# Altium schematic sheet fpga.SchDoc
size A2
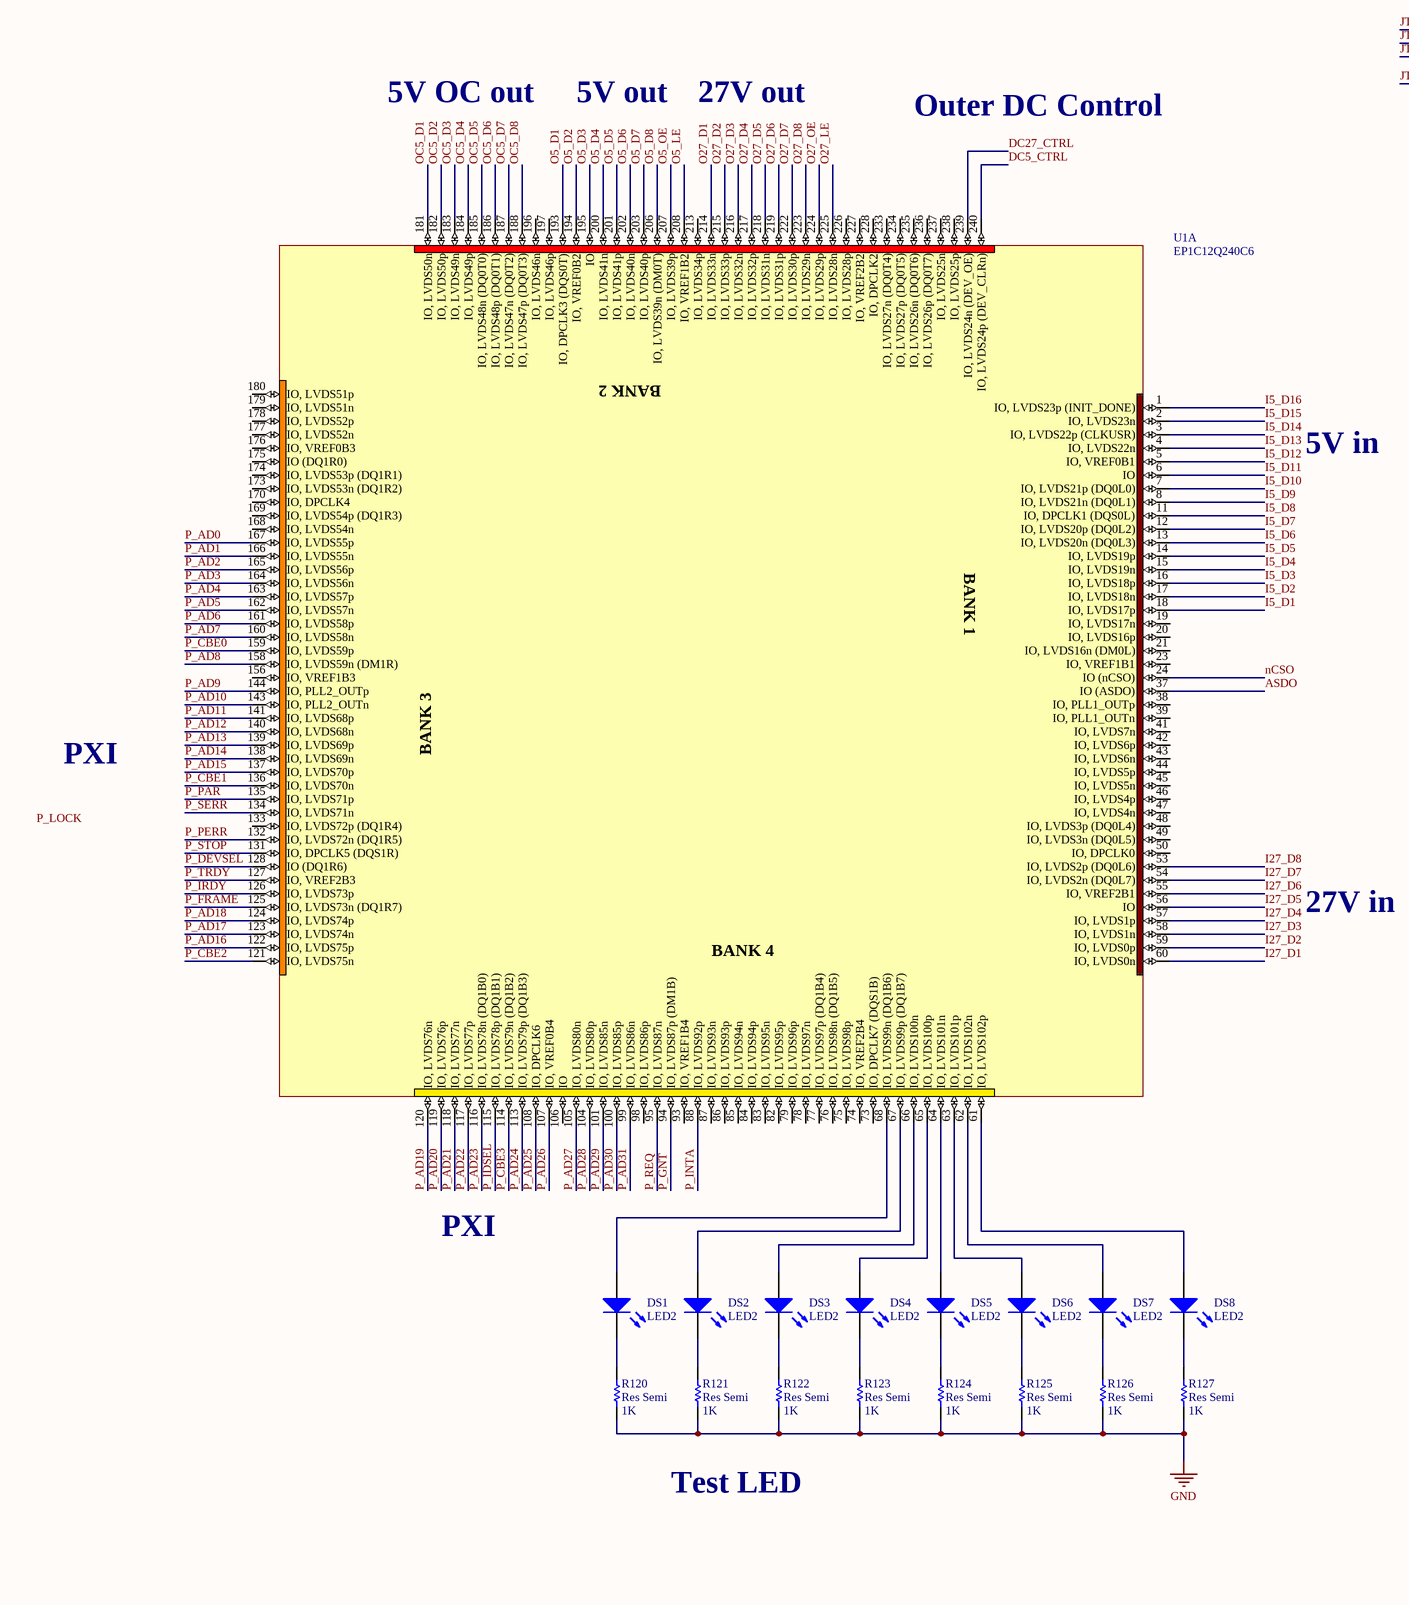
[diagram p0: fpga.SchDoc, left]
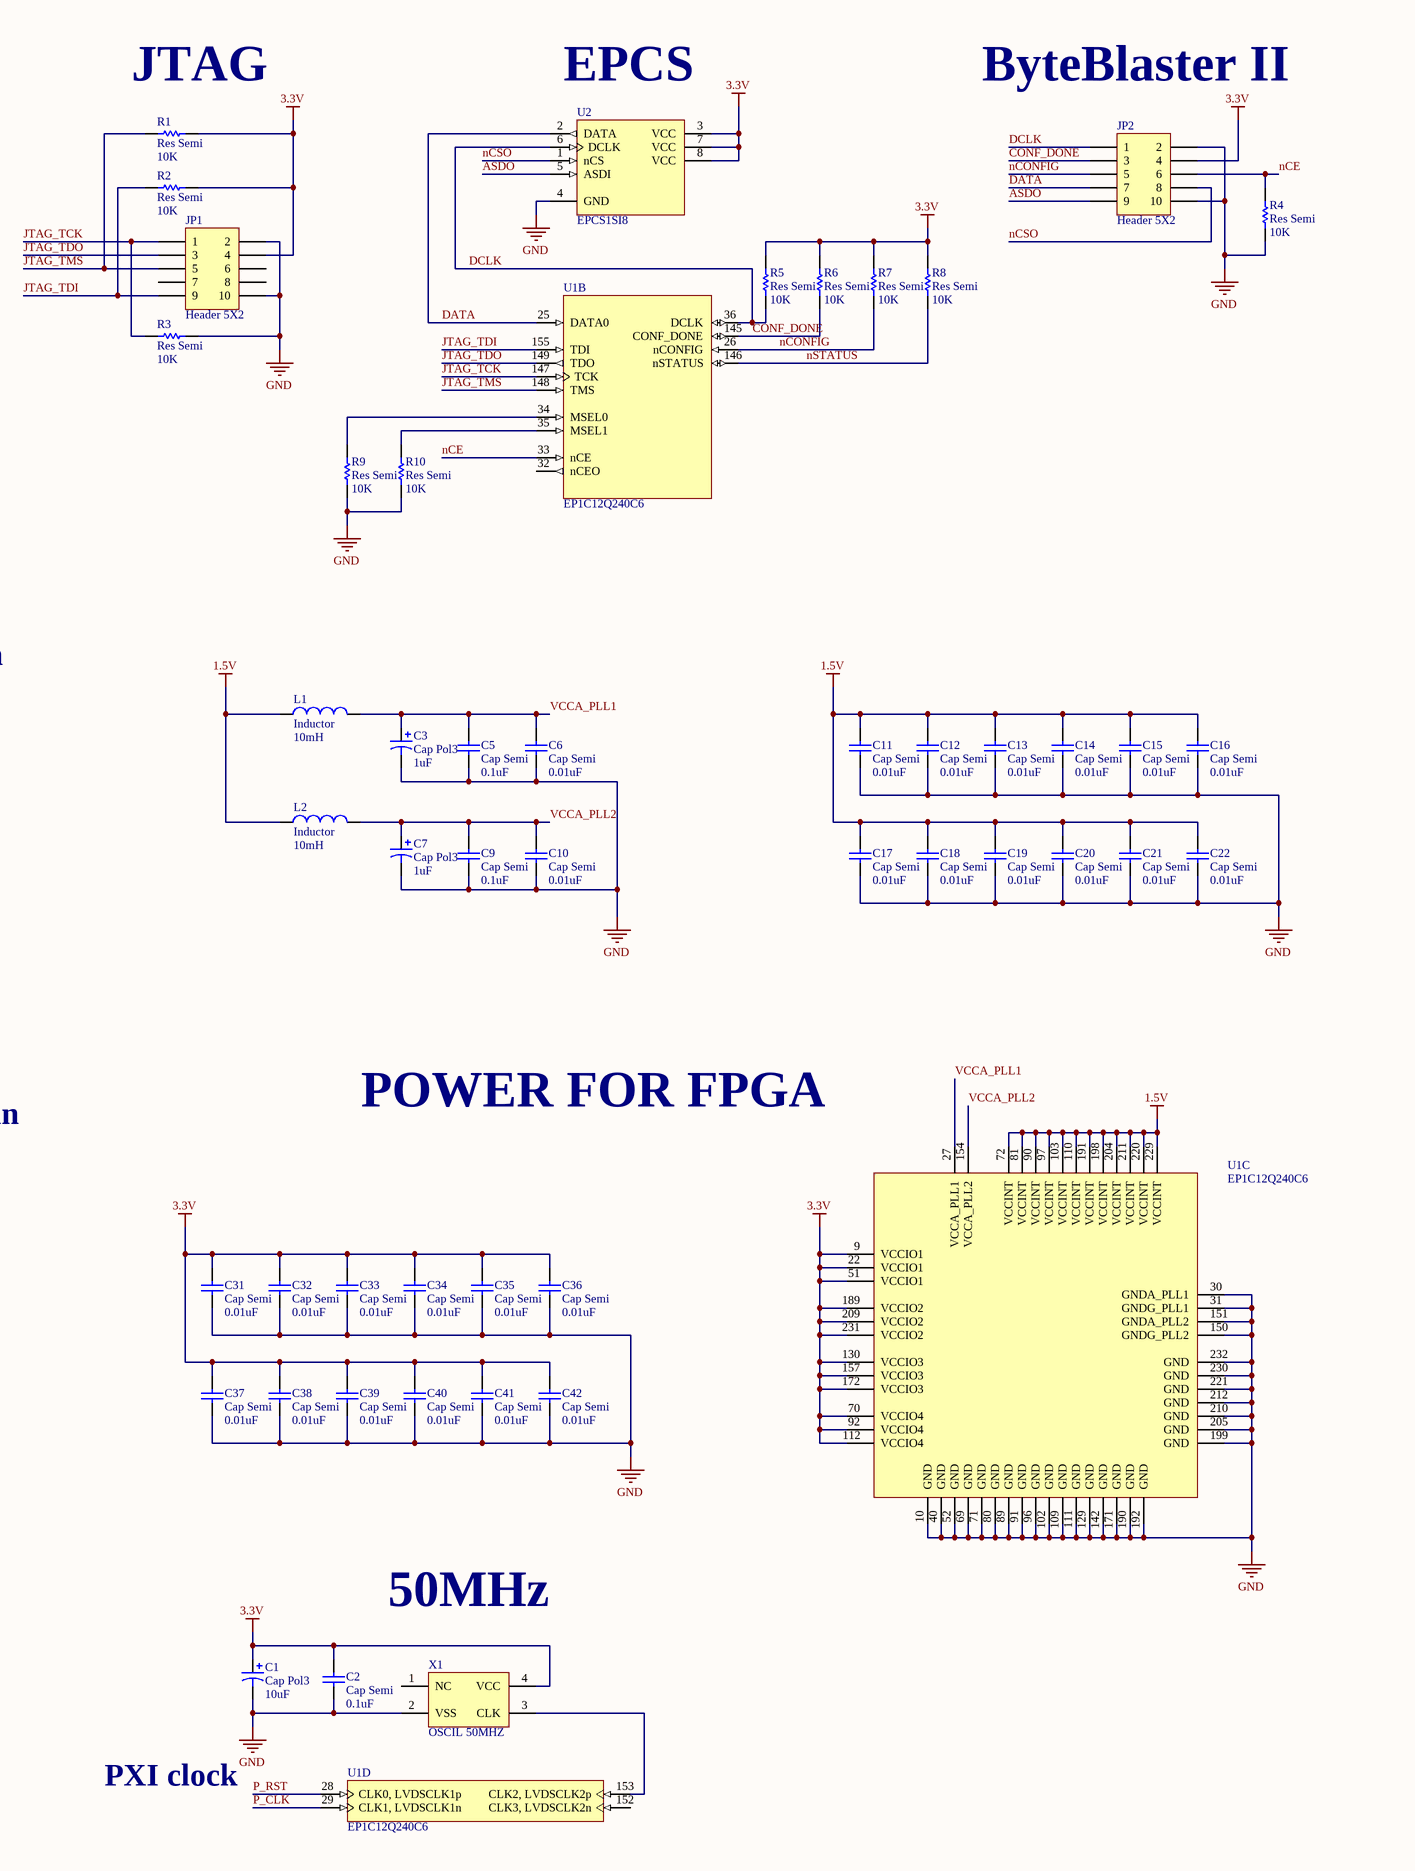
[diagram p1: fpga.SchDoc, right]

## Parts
C1  Cap Pol3  value 10uF  [CC3216-1206]
C2  Cap Semi  value 0.1uF  [1608[0603]]
C3  Cap Pol3  value 1uF  [CC3216-1206]
C5  Cap Semi  value 0.1uF  [1608[0603]]
C6  Cap Semi  value 0.01uF  [1608[0603]]
C7  Cap Pol3  value 1uF  [CC3216-1206]
C9  Cap Semi  value 0.1uF  [1608[0603]]
C10  Cap Semi  value 0.01uF  [1608[0603]]
C11  Cap Semi  value 0.01uF  [1608[0603]]
C12  Cap Semi  value 0.01uF  [1608[0603]]
C13  Cap Semi  value 0.01uF  [1608[0603]]
C14  Cap Semi  value 0.01uF  [1608[0603]]
C15  Cap Semi  value 0.01uF  [1608[0603]]
C16  Cap Semi  value 0.01uF  [1608[0603]]
C17  Cap Semi  value 0.01uF  [1608[0603]]
C18  Cap Semi  value 0.01uF  [1608[0603]]
C19  Cap Semi  value 0.01uF  [1608[0603]]
C20  Cap Semi  value 0.01uF  [1608[0603]]
C21  Cap Semi  value 0.01uF  [1608[0603]]
C22  Cap Semi  value 0.01uF  [1608[0603]]
C31  Cap Semi  value 0.01uF  [1608[0603]]
C32  Cap Semi  value 0.01uF  [1608[0603]]
C33  Cap Semi  value 0.01uF  [1608[0603]]
C34  Cap Semi  value 0.01uF  [1608[0603]]
C35  Cap Semi  value 0.01uF  [1608[0603]]
C36  Cap Semi  value 0.01uF  [1608[0603]]
C37  Cap Semi  value 0.01uF  [1608[0603]]
C38  Cap Semi  value 0.01uF  [1608[0603]]
C39  Cap Semi  value 0.01uF  [1608[0603]]
C40  Cap Semi  value 0.01uF  [1608[0603]]
C41  Cap Semi  value 0.01uF  [1608[0603]]
C42  Cap Semi  value 0.01uF  [1608[0603]]
DS1  LED2  [CC1608-0603]
DS2  LED2  [CC1608-0603]
DS3  LED2  [CC1608-0603]
DS4  LED2  [CC1608-0603]
DS5  LED2  [CC1608-0603]
DS6  LED2  [CC1608-0603]
DS7  LED2  [CC1608-0603]
DS8  LED2  [CC1608-0603]
JP1  Header 5X2  [HDR2X5]
JP2  Header 5X2  [HDR2X5]
L1  Inductor  value 10mH  [C1608-0603]
L2  Inductor  value 10mH  [C1608-0603]
R1  Res Semi  value 10K  [1608[0603]]
R2  Res Semi  value 10K  [1608[0603]]
R3  Res Semi  value 10K  [1608[0603]]
R4  Res Semi  value 10K  [1608[0603]]
R5  Res Semi  value 10K  [1608[0603]]
R6  Res Semi  value 10K  [1608[0603]]
R7  Res Semi  value 10K  [1608[0603]]
R8  Res Semi  value 10K  [1608[0603]]
R9  Res Semi  value 10K  [1608[0603]]
R10  Res Semi  value 10K  [1608[0603]]
R120  Res Semi  value 1K  [1608[0603]]
R121  Res Semi  value 1K  [1608[0603]]
R122  Res Semi  value 1K  [1608[0603]]
R123  Res Semi  value 1K  [1608[0603]]
R124  Res Semi  value 1K  [1608[0603]]
R125  Res Semi  value 1K  [1608[0603]]
R126  Res Semi  value 1K  [1608[0603]]
R127  Res Semi  value 1K  [1608[0603]]
U1  EP1C12Q240C6  [PQFP240]  (parts A,B,C,D of 4)
U2  EPCS1SI8  [SOIC8_L]
X1  OSCIL 50MHZ  [OSC -BIG]

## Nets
1.5V: C11.2 C12.2 C13.2 C14.2 C15.2 C16.2 C17.2 C18.2 C19.2 C20.2 C21.2 C22.2 L1.1 L2.1 U1.72(VCCINT) U1.81(VCCINT) U1.90(VCCINT) U1.97(VCCINT) U1.103(VCCINT) U1.110(VCCINT) U1.191(VCCINT) U1.198(VCCINT) U1.204(VCCINT) U1.211(VCCINT) U1.220(VCCINT) U1.229(VCCINT)
3.3V: C1.1 C2.2 C31.2 C32.2 C33.2 C34.2 C35.2 C36.2 C37.2 C38.2 C39.2 C40.2 C41.2 C42.2 JP1.4 JP2.4 R1.2 R2.2 R5.1 R6.1 R7.1 R8.1 U1.9(VCCIO1) U1.22(VCCIO1) U1.51(VCCIO1) U1.70(VCCIO4) U1.92(VCCIO4) U1.112(VCCIO4) U1.130(VCCIO3) U1.157(VCCIO3) U1.172(VCCIO3) U1.189(VCCIO2) U1.209(VCCIO2) U1.231(VCCIO2) U2.3(VCC) U2.7(VCC) U2.8(VCC) X1.4(VCC)
GND: C1.2 C2.1 C3.2 C5.1 C6.1 C7.2 C9.1 C10.1 C11.1 C12.1 C13.1 C14.1 C15.1 C16.1 C17.1 C18.1 C19.1 C20.1 C21.1 C22.1 C31.1 C32.1 C33.1 C34.1 C35.1 C36.1 C37.1 C38.1 C39.1 C40.1 C41.1 C42.1 JP1.2 JP1.10 JP2.2 JP2.10 R3.2 R4.1 R9.2 R10.2 R120.2 R121.2 R122.2 R123.2 R124.2 R125.2 R126.2 R127.2 U1.10(GND) U1.30(GNDA_PLL1) U1.31(GNDG_PLL1) U1.40(GND) U1.52(GND) U1.69(GND) U1.71(GND) U1.80(GND) U1.89(GND) U1.91(GND) U1.96(GND) U1.102(GND) U1.109(GND) U1.111(GND) U1.129(GND) U1.142(GND) U1.150(GNDG_PLL2) U1.151(GNDA_PLL2) U1.171(GND) U1.190(GND) U1.192(GND) U1.199(GND) U1.205(GND) U1.210(GND) U1.212(GND) U1.221(GND) U1.230(GND) U1.232(GND) U2.4(GND) X1.2(VSS)
ASDO: JP2.9 U1.37(IO_(ASDO)) U2.5(ASDI)
CONF_DONE: JP2.3 R6.2 U1.145(CONF_DONE)
DATA: JP2.7 U1.25(DATA0) U2.2(DATA)
DC5_CTRL: U1.240(IO,_LVDS24p_(DEV_CLRn))
DC27_CTRL: U1.239(IO,_LVDS24n_(DEV_OE))
DCLK: JP2.1 R5.2 U1.36(DCLK) U2.6(DCLK)
I5_D1: U1.18(IO,_LVDS17p)
I5_D2: U1.17(IO,_LVDS18n)
I5_D3: U1.16(IO,_LVDS18p)
I5_D4: U1.15(IO,_LVDS19n)
I5_D5: U1.14(IO,_LVDS19p)
I5_D6: U1.13(IO,_LVDS20n_(DQ0L3))
I5_D7: U1.12(IO,_LVDS20p_(DQ0L2))
I5_D8: U1.11(IO,_DPCLK1_(DQS0L))
I5_D9: U1.8(IO,_LVDS21n_(DQ0L1))
I5_D10: U1.7(IO,_LVDS21p_(DQ0L0))
I5_D11: U1.6(IO)
I5_D12: U1.5(IO,_VREF0B1)
I5_D13: U1.4(IO,_LVDS22n)
I5_D14: U1.3(IO,_LVDS22p_(CLKUSR))
I5_D15: U1.2(IO,_LVDS23n)
I5_D16: U1.1(IO,_LVDS23p_(INIT_DONE))
I27_D1: U1.60(IO,_LVDS0n)
I27_D2: U1.59(IO,_LVDS0p)
I27_D3: U1.58(IO,_LVDS1n)
I27_D4: U1.57(IO,_LVDS1p)
I27_D5: U1.56(IO)
I27_D6: U1.55(IO,_VREF2B1)
I27_D7: U1.54(IO,_LVDS2n_(DQ0L7))
I27_D8: U1.53(IO,_LVDS2p_(DQ0L6))
JTAG_TCK: JP1.1 R3.1 U1.147(TCK)
JTAG_TDI: JP1.9 R2.1 U1.155(TDI)
JTAG_TDO: JP1.3 U1.149(TDO)
JTAG_TMS: JP1.5 R1.1 U1.148(TMS)
nCE: JP2.6 R4.2 U1.33(nCE)
nCONFIG: JP2.5 R7.2 U1.26(nCONFIG)
nCSO: JP2.8 U1.24(IO_(nCSO)) U2.1(nCS)
nSTATUS: R8.2 U1.146(nSTATUS)
O5_D1: U1.193(IO,_DPCLK3_(DQS0T))
O5_D2: U1.194(IO,_VREF0B2)
O5_D3: U1.195(IO)
O5_D4: U1.200(IO,_LVDS41n)
O5_D5: U1.201(IO,_LVDS41p)
O5_D6: U1.202(IO,_LVDS40n)
O5_D7: U1.203(IO,_LVDS40p)
O5_D8: U1.206(IO,_LVDS39n_(DM0T))
O5_LE: U1.208(IO,_VREF1B2)
O5_OE: U1.207(IO,_LVDS39p)
O27_D1: U1.214(IO,_LVDS33n)
O27_D2: U1.215(IO,_LVDS33p)
O27_D3: U1.216(IO,_LVDS32n)
O27_D4: U1.217(IO,_LVDS32p)
O27_D5: U1.218(IO,_LVDS31n)
O27_D6: U1.219(IO,_LVDS31p)
O27_D7: U1.222(IO,_LVDS30p)
O27_D8: U1.223(IO,_LVDS29n)
O27_LE: U1.225(IO,_LVDS28n)
O27_OE: U1.224(IO,_LVDS29p)
OC5_D1: U1.181(IO,_LVDS50n)
OC5_D2: U1.182(IO,_LVDS50p)
OC5_D3: U1.183(IO,_LVDS49n)
OC5_D4: U1.184(IO,_LVDS49p)
OC5_D5: U1.185(IO,_LVDS48n_(DQ0T0))
OC5_D6: U1.186(IO,_LVDS48p_(DQ0T1))
OC5_D7: U1.187(IO,_LVDS47n_(DQ0T2))
OC5_D8: U1.188(IO,_LVDS47p_(DQ0T3))
P_AD0: U1.167(IO,_LVDS55p)
P_AD1: U1.166(IO,_LVDS55n)
P_AD2: U1.165(IO,_LVDS56p)
P_AD3: U1.164(IO,_LVDS56n)
P_AD4: U1.163(IO,_LVDS57p)
P_AD5: U1.162(IO,_LVDS57n)
P_AD6: U1.161(IO,_LVDS58p)
P_AD7: U1.160(IO,_LVDS58n)
P_AD8: U1.158(IO,_LVDS59n_(DM1R))
P_AD9: U1.144(IO,_PLL2_OUTp)
P_AD10: U1.143(IO,_PLL2_OUTn)
P_AD11: U1.141(IO,_LVDS68p)
P_AD12: U1.140(IO,_LVDS68n)
P_AD13: U1.139(IO,_LVDS69p)
P_AD14: U1.138(IO,_LVDS69n)
P_AD15: U1.137(IO,_LVDS70p)
P_AD16: U1.122(IO,_LVDS75p)
P_AD17: U1.123(IO,_LVDS74n)
P_AD18: U1.124(IO,_LVDS74p)
P_AD19: U1.120(IO,_LVDS76n)
P_AD20: U1.119(IO,_LVDS76p)
P_AD21: U1.118(IO,_LVDS77n)
P_AD22: U1.117(IO,_LVDS77p)
P_AD23: U1.116(IO,_LVDS78n_(DQ1B0))
P_AD24: U1.113(IO,_LVDS79p_(DQ1B3))
P_AD25: U1.108(IO,_DPCLK6)
P_AD26: U1.107(IO,_VREF0B4)
P_AD27: U1.105(IO,_LVDS80n)
P_AD28: U1.104(IO,_LVDS80p)
P_AD29: U1.101(IO,_LVDS85n)
P_AD30: U1.100(IO,_LVDS85p)
P_AD31: U1.99(IO,_LVDS86n)
P_CBE0: U1.159(IO,_LVDS59p)
P_CBE1: U1.136(IO,_LVDS70n)
P_CBE2: U1.121(IO,_LVDS75n)
P_CBE3: U1.114(IO,_LVDS79n_(DQ1B2))
P_CLK: U1.29(CLK1,_LVDSCLK1n)
P_DEVSEL: U1.128(IO_(DQ1R6))
P_FRAME: U1.125(IO,_LVDS73n_(DQ1R7))
P_GNT: U1.94(IO,_LVDS87p_(DM1B))
P_IDSEL: U1.115(IO,_LVDS78p_(DQ1B1))
P_INTA: U1.88(IO,_LVDS92p)
P_IRDY: U1.126(IO,_LVDS73p)
P_PAR: U1.135(IO,_LVDS71p)
P_PERR: U1.132(IO,_LVDS72n_(DQ1R5))
P_REQ: U1.95(IO,_LVDS87n)
P_RST: U1.28(CLK0,_LVDSCLK1p)
P_SERR: U1.134(IO,_LVDS71n)
P_STOP: U1.131(IO,_DPCLK5_(DQS1R))
P_TRDY: U1.127(IO,_VREF2B3)
VCCA_PLL1: C3.1 C5.2 C6.2 L1.2 U1.27(VCCA_PLL1)
VCCA_PLL2: C7.1 C9.2 C10.2 L2.2 U1.154(VCCA_PLL2)
NetDS1_1: DS1.1(A) U1.68(IO,_LVDS99n_(DQ1B6))
NetDS1_2: DS1.2(K) R120.1
NetDS2_1: DS2.1(A) U1.67(IO,_LVDS99p_(DQ1B7))
NetDS2_2: DS2.2(K) R121.1
NetDS3_1: DS3.1(A) U1.66(IO,_LVDS100n)
NetDS3_2: DS3.2(K) R122.1
NetDS4_1: DS4.1(A) U1.65(IO,_LVDS100p)
NetDS4_2: DS4.2(K) R123.1
NetDS5_1: DS5.1(A) U1.64(IO,_LVDS101n)
NetDS5_2: DS5.2(K) R124.1
NetDS6_1: DS6.1(A) U1.63(IO,_LVDS101p)
NetDS6_2: DS6.2(K) R125.1
NetDS7_1: DS7.1(A) U1.62(IO,_LVDS102n)
NetDS7_2: DS7.2(K) R126.1
NetDS8_1: DS8.1(A) U1.61(IO,_LVDS102p)
NetDS8_2: DS8.2(K) R127.1
NetR9_1: R9.1 U1.34(MSEL0)
NetR10_1: R10.1 U1.35(MSEL1)
NetU1_153: U1.153(CLK2,_LVDSCLK2p) X1.3(CLK)

Not connected (* = marked no-connect by the designer): JP1 6 7 8; U1 19(IO,_LVDS17n) 20(IO,_LVDS16p) 21(IO,_LVDS16n_(DM0L)) 23(IO,_VREF1B1) 32(nCEO) 38(IO,_PLL1_OUTp) 39(IO,_PLL1_OUTn) 41(IO,_LVDS7n) 42(IO,_LVDS6p) 43(IO,_LVDS6n) 44(IO,_LVDS5p) 45(IO,_LVDS5n) 46(IO,_LVDS4p) 47(IO,_LVDS4n) 48(IO,_LVDS3p_(DQ0L4)) 49(IO,_LVDS3n_(DQ0L5)) 50(IO,_DPCLK0) 73(IO,_DPCLK7_(DQS1B)) 74(IO,_VREF2B4) 75(IO,_LVDS98p) 76(IO,_LVDS98n_(DQ1B5)) 77(IO,_LVDS97p_(DQ1B4)) 78(IO,_LVDS97n) 79(IO,_LVDS96p) 82(IO,_LVDS95p) 83(IO,_LVDS95n) 84(IO,_LVDS94p) 85(IO,_LVDS94n) 86(IO,_LVDS93p) 87(IO,_LVDS93n) 93(IO,_VREF1B4) 98(IO,_LVDS86p) 106(IO) 133(IO,_LVDS72p_(DQ1R4)) 152(CLK3,_LVDSCLK2n) 156(IO,_VREF1B3) 168(IO,_LVDS54n) 169(IO,_LVDS54p_(DQ1R3)) 170(IO,_DPCLK4) 173(IO,_LVDS53n_(DQ1R2)) 174(IO,_LVDS53p_(DQ1R1)) 175(IO_(DQ1R0)) 176(IO,_VREF0B3) 177(IO,_LVDS52n) 178(IO,_LVDS52p) 179(IO,_LVDS51n) 180(IO,_LVDS51p) 196(IO,_LVDS46n) 197(IO,_LVDS46p) 213(IO,_LVDS34p) 226(IO,_LVDS28p) 227(IO,_VREF2B2) 228(IO,_DPCLK2) 233(IO,_LVDS27n_(DQ0T4)) 234(IO,_LVDS27p_(DQ0T5)) 235(IO,_LVDS26n_(DQ0T6)) 236(IO,_LVDS26p_(DQ0T7)) 237(IO,_LVDS25n) 238(IO,_LVDS25p); X1 1(NC)

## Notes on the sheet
- (near R1) JTAG
- (near U2) EPCS
- ByteBlaster II
- 5V OC out
- 5V out
- 27V out
- Outer DC Control
- 5V in
- PXI
- 27V in
- POWER FOR FPGA
- 50MHz
- Test LED
- PXI clock
- Labels drawn without touching a wire or pin: P_LOCK

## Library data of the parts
C1 C3 C7 = Cap Pol3: Polarized Capacitor (Surface Mount)
C2 C5 C6 C9-C22 C31-C42 = Cap Semi: Capacitor (Semiconductor SIM Model)
DS1-DS8 = LED2: Typical RED, GREEN, YELLOW, AMBER GaAs LED
JP1 JP2 = Header 5X2: Header, 5-Pin, Dual row
L1 L2 = Inductor: Code_IEC: 1005
R1-R10 R120-R127 = Res Semi: Semiconductor Resistor
U1 = EP1C12Q240C6: Cyclone Family, 1.5V FPGA, 173 I/O Pins, 2 x PLLs, Commercial Grade, Speed Grade 6; Package Information: Latest Revision: ver11.0, Feb-2003; Code - JEDEC: MS-029-GA
U2 = EPCS1SI8: EPCS1 Series, In-system programmable 3.3V serial configuration device, 8-Pin SOIC, 1-Megabit, Industrial Grade; Configures: Cyclone II, Stratix II, & Cyclone Devices
X1 = OSCIL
